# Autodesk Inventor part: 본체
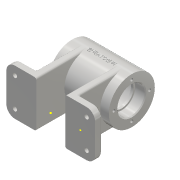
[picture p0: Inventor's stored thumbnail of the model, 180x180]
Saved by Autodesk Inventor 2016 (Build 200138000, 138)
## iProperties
Created: 2017-02
Part Number: 본체
Material: 알루미늄 6061
Document SubType Name: Modeling
Designer: H
Mass: 352.777 g
Surface Area: 422.357 cm^2
Volume: 130.658 cm^3
Density: 2.7 g/cm^3
Appearance: 알루미늄 - 평지
Author: H
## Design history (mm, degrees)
sketch "스케치1"
  geometry: L1 (52, -27)-(52, 27); L2 (-52, 27)-(-52, -27); L3 (0, 0)-(0, -48.333); L4 (17, 27)-(17, -27); L5 (-17, 27)-(-17, -27); L6 (52, 27)-(17, 27); L7 (-17, 27)-(-52, 27); L8 (-52, -27)-(-17, -27); L9 (17, -27)-(52, -27)
  constraints: 18 end point, 6 perpendicular, 5 parallel, 2 horizontal, 1 vertical
  dimensions: "d0" = 104 distance between parallel lines of L2 L1; "d2" = 52 distance between parallel lines of L1 L3; "d3" = 17 distance between parallel lines of L3 L4; "d4" = 17 distance between parallel lines of L3 L5; "d5" = 54 distance between parallel lines of L8 L7; "d6" = 54 distance between parallel lines of L6 L9
extrude "돌출1" new body sketch "스케치1" distance "d7" = 8; taper "d8" = 0 deg
fillet "모깎기1" dims "d9" = 10
sketch "스케치3"
  geometry: L1 (-17, -27)-(-17, 27) reference; L2 (17, 27)-(17, -27) reference; L3 (-42, 27)-(-17, 27) reference; L4 (-25, 27)-(-25, -27); L5 (-42, -27)-(-17, -27) reference; L6 (17, 27)-(42, 27) reference; L7 (25, 27)-(25, -27); L8 (42, -27)-(17, -27) reference; 1 further point
  constraints: 4 end point, 4 point on line, 2 perpendicular
  dimensions: "d10" = 8 distance between parallel lines of L1 L4; "d11" = 8 distance between parallel lines of L2 L7
extrude "돌출2" join sketch "스케치3" distance "d12" = 52; taper "d13" = 0 deg
sketch "스케치4"
  geometry: L1 (-25, 8)-(-25, 60) reference; L2 (25, 60)-(17, 60) reference; L3 (-17, 0)-(-42, 0) reference; L4 (25, 8)-(25, 60) reference; L5 (-35, 60)-(35, 60); L6 (-35, 60)-(-35, 87); L7 (-35, 87)-(35, 87); L8 (35, 87)-(35, 60); L9 (0, 0)-(0, 139.91); L10 (0, 0)-(139.91, 0)
  constraints: 12 end point, 3 perpendicular, 2 horizontal, 1 vertical
  dimensions: "d15" = 60 distance between parallel lines of L5 L3; "d18" = 35 distance between parallel lines of L9 L6; "d19" = 70 distance between parallel lines of L8 L6; "d20" = 54 diameter of L7 L5
revolve "회전1" sketch "스케치4" stored, may be unused: angle "d21" = 90 deg
sketch "스케치5"
  geometry: 1 further point
sketch "스케치6"
  geometry: C1 r 27 at (0, 0) reference; C2 r 16 at (0, 0); 1 further point
  constraints: 1 centre point, 1 coincident
  dimensions: "d22" = 32 diameter of C2
extrude "돌출3" cut sketch "스케치6" distance "d23" = 12; taper "d24" = 0 deg
sketch "스케치7"
  geometry: C1 r 27 at (0, 0) reference; C2 r 14 at (0, 0); 1 further point
  constraints: 1 centre point, 1 coincident
  dimensions: "d25" = 28 diameter of C2
extrude "돌출4" cut sketch "스케치7" distance "d26" = 3; taper "d27" = 0 deg
sketch "스케치8"
  geometry: C1 r 27 at (0, 0) reference; C2 r 22 at (0, 0); 1 further point
  constraints: 1 centre point, 1 coincident
  dimensions: "d28" = 44 diameter of C2
extrude "돌출5" cut sketch "스케치8" distance "d29" = 40; taper "d30" = 0 deg
sketch "스케치9"
  geometry: C1 r 27 at (0, 0) reference; C2 r 16 at (0, 0); 1 further point
  constraints: 1 centre point, 1 coincident
  dimensions: "d31" = 32 diameter of C2
extrude "돌출6" cut sketch "스케치9" distance "d32" = 12; taper "d33" = 0 deg
sketch "스케치10"
  geometry: C1 r 16 at (0, 0) reference; C2 r 27 at (0, 0) reference; C3 r 14 at (0, 0); 1 further point
  constraints: 1 centre point, 1 coincident
  dimensions: "d34" = 28 diameter of C3
extrude "돌출7" cut sketch "스케치10" distance "d35" = 12; taper "d36" = 0 deg
sketch "스케치11"
  geometry: L1 (-10, 92)-(-5, 92); L2 (-5, 92)-(-5, 83.453); L3 (-5, 83.453)-(-10, 83.453); L4 (-10, 83.453)-(-10, 92); L5 (-35, 33)-(-35, 87) reference; L6 (-35, 87)-(35, 87) reference; 1 further point
  constraints: 8 end point, 2 parallel, 1 horizontal, 1 perpendicular
  dimensions: "d37" = 25 distance between parallel lines of L5 L4; "d38" = 5 distance between parallel lines of L6 L1; "d39" = 10 diameter of L2 L4
revolve "회전2" sketch "스케치11" stored, may be unused: angle "d40" = 90 deg
sketch "스케치12"
  geometry: C1 r 5 at (0, 0) reference; 1 further point
hole "구멍1" sketch "스케치12" at (0, 0) diameter "d41" = 5.188; stored, may be unused: countersink angle "d45" = 90 deg, drill point angle "d47" = 118 deg; dims "d42" = 12, "d43" = 4, "d44" = 2, "d46" = 20.25
sketch "스케치13" dims "d48" = 42
  geometry: L1 (0, 0)-(0, 31.509); C1 r 16 at (0, 0) reference; C2 r 27 at (0, 0) reference; C3 r 16 at (0, 0) reference; 2 further points
  constraints: 2 end point, 1 coincident, 1 point on line, 1 vertical, 1 vertical alignment, 2 other
hole "구멍2" sketch "스케치13" at (0, 21) diameter "d49" = 3.242; stored, may be unused: countersink angle "d53" = 90 deg, drill point angle "d55" = 118 deg; dims "d50" = 8, "d51" = 4, "d52" = 2, "d54" = 10
sketch "스케치14"
  geometry: L1 (43.011, -18.187)-(38.108, -21.371); L2 (38.108, -21.371)-(34.84, -16.339); L3 (34.84, -16.339)-(39.744, -13.155); L4 (39.744, -13.155)-(43.011, -18.187); L5 (60, 0)-(18.199, 0); L6 (39.744, -13.155)-(60, 0); C1 r 27 at (60, 0) reference; C2 r 14 at (60, 0) reference; 1 further point
  constraints: 12 end point, 2 parallel, 1 horizontal, 1 perpendicular
  dimensions: "d59" = 33 deg angle of L5 L3; "d60" = 30 distance from line of L5.start L2; "d61" = 5.84691 distance between parallel lines of L2 L4; "d62" = 12 diameter of L1 L3; "d100" = 33 deg angle of L5 L6
revolve "회전3" sketch "스케치14" stored, may be unused: angle "d63" = 90 deg
sketch "스케치15"
  geometry: C1 r 6 at (0, 0) reference; 1 further point
hole "구멍3" sketch "스케치15" at (0, 0) diameter "d64" = 5.188; stored, may be unused: countersink angle "d68" = 90 deg, drill point angle "d70" = 118 deg; dims "d65" = 12, "d66" = 4, "d67" = 2, "d69" = 16
sketch "스케치16"
  geometry: 1 further point
node "작업 평면1"
sketch "스케치17"
  geometry: L1 (-35, 87)-(35, 87) reference; L2 (-35, 33)-(-35, 87) reference; 2 further points
  constraints: 1 other
  dimensions: "d72" = 27 distance from line of L1 point (0, 60); "d73" = 35 distance from line of point (0, 60) L2
feature "엠보싱1" sketch "스케치17" dims "d74" = 0.5, "d75" = 0
sketch "스케치18"
  geometry: A1 r 10 centre (42, 17) between (52, 17) and (42, 27) reference; A2 r 10 centre (42, -17) between (42, -27) and (52, -17) reference; A3 r 10 centre (-42, -17) between (-52, -17) and (-42, -27) reference; A4 r 10 centre (-42, 17) between (-42, 27) and (-52, 17) reference; 1 further point
hole "구멍4" sketch "스케치18" at (42, 17), (42, -17), (-42, -17), (-42, 17) diameter "d76" = 5; stored, may be unused: countersink angle "d80" = 90 deg, drill point angle "d82" = 118 deg; dims "d77" = 12, "d78" = 9, "d79" = 3, "d81" = 16
sketch "스케치19"
  geometry: L1 (39.402, 12.5)-(36.804, 17); L2 (36.804, 17)-(39.402, 21.5); L3 (39.402, 21.5)-(44.598, 21.5); L4 (44.598, 21.5)-(47.196, 17); L5 (47.196, 17)-(44.598, 12.5); L6 (44.598, 12.5)-(39.402, 12.5); L7 (39.402, -21.5)-(36.804, -17); L8 (36.804, -17)-(39.402, -12.5); L9 (39.402, -12.5)-(44.598, -12.5); L10 (44.598, -12.5)-(47.196, -17); L11 (47.196, -17)-(44.598, -21.5); L12 (44.598, -21.5)-(39.402, -21.5); L13 (-44.598, -21.5)-(-47.196, -17); L14 (-47.196, -17)-(-44.598, -12.5); L15 (-44.598, -12.5)-(-39.402, -12.5); L16 (-39.402, -12.5)-(-36.804, -17); L17 (-36.804, -17)-(-39.402, -21.5); L18 (-39.402, -21.5)-(-44.598, -21.5); L19 (-44.598, 12.5)-(-47.196, 17); L20 (-47.196, 17)-(-44.598, 21.5); L21 (-44.598, 21.5)-(-39.402, 21.5); L22 (-39.402, 21.5)-(-36.804, 17); L23 (-36.804, 17)-(-39.402, 12.5); L24 (-39.402, 12.5)-(-44.598, 12.5); C1 r 2.5 at (42, -17) reference; C2 r 2.5 at (-42, -17) reference; C3 r 2.5 at (-42, 17) reference; 15 further points
  constraints: 48 end point, 5 coincident, 4 midpoint, 4 vertical alignment, 1 point on line, 56 other
extrude "돌출8" cut sketch "스케치19" distance "d83" = 3; taper "d84" = 0 deg
extrude "돌출9" cut sketch "스케치19" distance "d85" = 3; taper "d86" = 0 deg
fillet "모깎기2" dims "d87" = 2
fillet "모깎기3" dims "d88" = 2
fillet "모깎기4" dims "d89" = 2
fillet "모깎기5" dims "d90" = 3
fillet "모깎기6" dims "d91" = 0.3
chamfer "모따기1" distance "d92" = 1; stored, may be unused: second distance "d93" = 2, angle "d94" = 45 deg
chamfer "모따기2" distance "d95" = 1; stored, may be unused: second distance "d96" = 2, angle "d97" = 45 deg
fillet "모깎기7" dims "d98" = 2
node "솔리드1"
pattern_circular "원형 패턴1" dims angle "d57" = 360 deg
mirror "대칭1"
node "투영된 루프1"
node "투영된 루프2"
node "투영된 루프3"
other parameters: "d1" = 54, "d71" = 32.5
